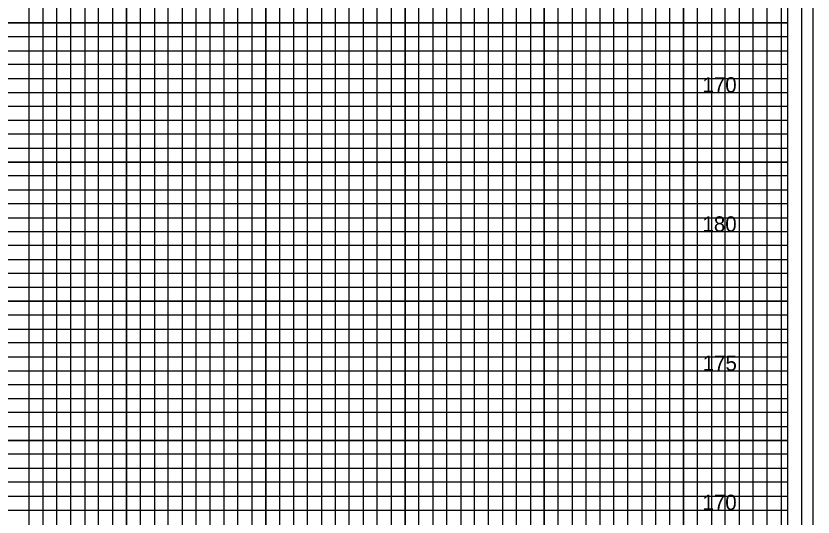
# Model space of a CAD drawing. Extents: x -4 to 103, y -2 to 209.
# Drawn here: x 74.78 to 103.4, y 103.07 to 121.08 of the extents above; entities that cross this region are included whole.
import ezdxf

# ---------------------------------------------------------------- set-up
doc = ezdxf.new("R2010")
doc.units = 0
for name, color, linetype in [('Prop XS Elevation Labels', 7, 'Continuous'), ('Sheet Cross Section CELL', 7, 'Continuous'), ('Sheet Cross Section Grid Major CELL', 7, 'Continuous'), ('Sheet Cross Section Grid Middle CELL', 7, 'Continuous'), ('Sheet DOT Grid CELL', 7, 'Continuous'), ('Sheet Plot Border Inside CELL', 7, 'Continuous'), ('Sheet Plot Border Outside CELL', 7, 'Continuous')]:
    doc.layers.add(name, color=color, linetype=linetype)

msp = doc.modelspace()

# ---------------------------------------------------------------- linework, layer by layer
at = {"layer": 'Sheet Cross Section CELL'}
msp.add_lwpolyline([(102.5, 135.825), (0, 135.825), (0, 70.825), (102.5, 70.825)], close=True, dxfattribs=at)
at = {"layer": 'Sheet Cross Section Grid Major CELL'}
for points in [[(91.25, 70.825), (91.25, 134.25), (93.75, 134.25), (93.75, 70.825)], [(96.25, 70.825), (96.25, 134.25), (98.75, 134.25), (98.75, 70.825)], [(101.25, 70.825), (101.25, 134.25)], [(76.25, 70.825), (76.25, 132.825), (78.75, 132.825), (78.75, 70.825)], [(81.25, 70.825), (81.25, 132.825), (83.75, 132.825), (83.75, 70.825)], [(86.25, 70.825), (86.25, 132.825), (88.75, 132.825), (88.75, 70.825)], [(0, 118.325), (102.5, 118.325), (102.5, 120.825), (0, 120.825)], [(0, 113.325), (102.5, 113.325), (102.5, 115.825), (0, 115.825)], [(0, 108.325), (102.5, 108.325), (102.5, 110.825), (0, 110.825)], [(0, 103.325), (102.5, 103.325), (102.5, 105.825), (0, 105.825)]]:
    msp.add_lwpolyline(points, dxfattribs=at)
at = {"layer": 'Sheet Cross Section Grid Middle CELL'}
for points in [[(90.25, 70.825), (90.25, 134.25), (90.75, 134.25), (90.75, 70.825)], [(91.75, 70.825), (91.75, 134.25), (92.25, 134.25), (92.25, 70.825)], [(92.75, 70.825), (92.75, 134.25), (93.25, 134.25), (93.25, 70.825)], [(94.25, 70.825), (94.25, 134.25), (94.75, 134.25), (94.75, 70.825)], [(95.25, 70.825), (95.25, 134.25), (95.75, 134.25), (95.75, 70.825)], [(96.75, 70.825), (96.75, 134.25), (97.25, 134.25), (97.25, 70.825)], [(97.75, 70.825), (97.75, 134.25), (98.25, 134.25), (98.25, 70.825)], [(99.25, 70.825), (99.25, 134.25), (99.75, 134.25), (99.75, 70.825)], [(100.25, 70.825), (100.25, 134.25)], [(100.25, 134.25), (100.75, 134.25), (100.75, 70.825), (101.75, 70.825), (101.75, 134.25), (102.25, 134.25), (102.25, 70.825)], [(75.25, 70.825), (75.25, 132.825), (75.75, 132.825), (75.75, 70.825)], [(76.75, 70.825), (76.75, 132.825), (77.25, 132.825), (77.25, 70.825)], [(77.75, 70.825), (77.75, 132.825), (78.25, 132.825), (78.25, 70.825)], [(79.25, 70.825), (79.25, 132.825), (79.75, 132.825), (79.75, 70.825)], [(80.25, 70.825), (80.25, 132.825), (80.75, 132.825), (80.75, 70.825)], [(81.75, 70.825), (81.75, 132.825), (82.25, 132.825), (82.25, 70.825)], [(82.75, 70.825), (82.75, 132.825), (83.25, 132.825), (83.25, 70.825)], [(84.25, 70.825), (84.25, 132.825), (84.75, 132.825), (84.75, 70.825)], [(85.25, 70.825), (85.25, 132.825), (85.75, 132.825), (85.75, 70.825)], [(86.75, 70.825), (86.75, 132.825), (87.25, 132.825), (87.25, 70.825)], [(87.75, 70.825), (87.75, 132.825), (88.25, 132.825), (88.25, 70.825)], [(89.25, 70.825), (89.25, 132.825), (89.75, 132.825), (89.75, 70.825)], [(0, 119.825), (102.5, 119.825), (102.5, 120.325), (0, 120.325)], [(0, 118.825), (102.5, 118.825), (102.5, 119.325), (0, 119.325)], [(0, 117.325), (102.5, 117.325), (102.5, 117.825), (0, 117.825)], [(0, 116.325), (102.5, 116.325), (102.5, 116.825), (0, 116.825)], [(0, 114.825), (102.5, 114.825), (102.5, 115.325), (0, 115.325)], [(0, 113.825), (102.5, 113.825), (102.5, 114.325), (0, 114.325)], [(0, 112.325), (102.5, 112.325), (102.5, 112.825), (0, 112.825)], [(0, 111.325), (102.5, 111.325), (102.5, 111.825), (0, 111.825)], [(0, 109.825), (102.5, 109.825), (102.5, 110.325), (0, 110.325)], [(0, 108.825), (102.5, 108.825), (102.5, 109.325), (0, 109.325)], [(0, 107.325), (102.5, 107.325), (102.5, 107.825), (0, 107.825)], [(0, 106.325), (102.5, 106.325), (102.5, 106.825), (0, 106.825)], [(0, 104.825), (102.5, 104.825), (102.5, 105.325), (0, 105.325)], [(0, 103.825), (102.5, 103.825), (102.5, 104.325), (0, 104.325)]]:
    msp.add_lwpolyline(points, dxfattribs=at)
at = {"layer": 'Sheet DOT Grid CELL'}
for p, q in [((91.25, 70.825), (91.25, 134.25)), ((93.75, 70.825), (93.75, 134.25)), ((96.25, 70.825), (96.25, 134.25)), ((98.75, 70.825), (98.75, 134.25)), ((101.25, 70.825), (101.25, 134.25)), ((76.25, 70.825), (76.25, 132.825)), ((78.75, 70.825), (78.75, 132.825)), ((81.25, 70.825), (81.25, 132.825)), ((83.75, 70.825), (83.75, 132.825)), ((86.25, 70.825), (86.25, 132.825)), ((88.75, 70.825), (88.75, 132.825)), ((0, 120.825), (102.5, 120.825)), ((0, 118.325), (102.5, 118.325)), ((0, 115.825), (102.5, 115.825)), ((0, 113.325), (102.5, 113.325)), ((0, 110.825), (102.5, 110.825)), ((0, 108.325), (102.5, 108.325)), ((0, 105.825), (102.5, 105.825)), ((0, 103.325), (102.5, 103.325))]:
    msp.add_line(p, q, dxfattribs=at)
at = {"layer": 'Sheet Plot Border Inside CELL'}
msp.add_lwpolyline([(103, 136.825), (-2.8, 136.825), (-2.8, 69.825), (103, 69.825)], close=True, dxfattribs=at)
at = {"layer": 'Sheet Plot Border Outside CELL'}
msp.add_lwpolyline([(103.4, 138.225), (-3.5, 138.225), (-3.5, 68.4), (103.4, 68.4)], close=True, dxfattribs=at)

# ---------------------------------------------------------------- texts
at = {"layer": 'Prop XS Elevation Labels'}
for s, p in [('170', (99.42958, 118.325)), ('180', (99.42958, 113.325)), ('175', (99.43825, 108.325)), ('170', (99.42958, 103.325))]:
    msp.add_text(s, height=0.55, dxfattribs=at).set_placement(p)

doc.saveas('drawing.dxf')
